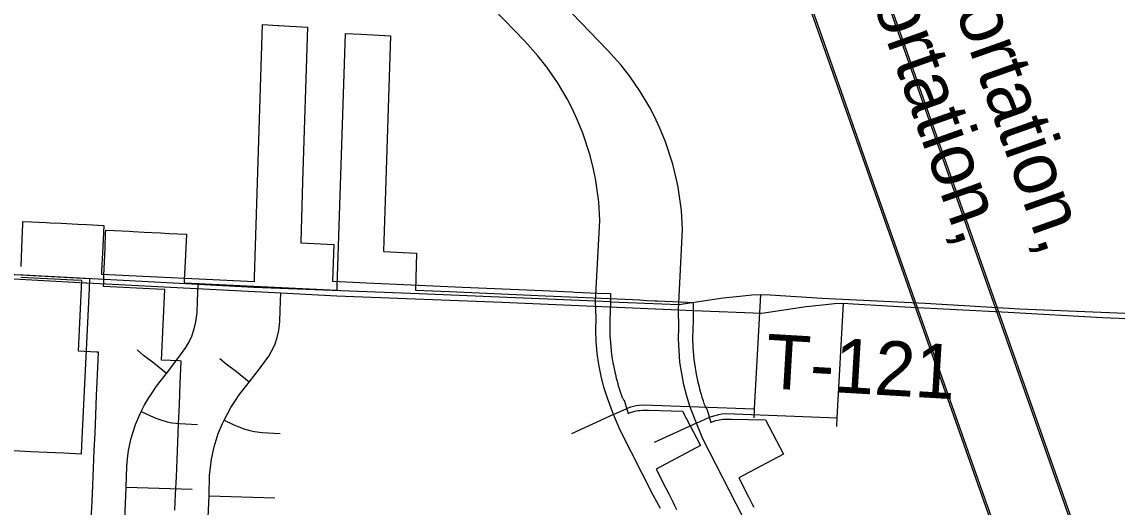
# Model space of a CAD drawing. Extents: x -38.2 to 41.9, y -4 to 24.9.
# Drawn here: x 5.806 to 6.95, y 18.257 to 18.764 of the extents above; entities that cross this region are included whole.
import ezdxf

# ---------------------------------------------------------------- set-up
doc = ezdxf.new("R2010")
doc.units = 0
for name, color, linetype in [('Default', 7, 'Continuous'), ('GM_X_City_Street', 7, 'Continuous'), ('GM_X_County_Road', 7, 'Continuous'), ('GM_X_Interstate_Location', 7, 'Continuous'), ('GM_X_Rail_Line', 7, 'Continuous'), ('GM_X_Rail_Line_Text', 7, 'Continuous'), ('GM_X_State_Location', 7, 'Continuous'), ('GM_X_Township_Road', 7, 'Continuous'), ('GM_X_Township_Road_Text', 7, 'Continuous')]:
    doc.layers.add(name, color=color, linetype=linetype)

msp = doc.modelspace()

# ---------------------------------------------------------------- linework, layer by layer
at = {"layer": 'Default'}
for points in [[(5.8055, 18.5083), (5.8066, 18.537), (5.8072, 18.5526), (5.8073, 18.5556), (5.8162, 18.5551), (5.8317, 18.5544), (5.8358, 18.5541), (5.8473, 18.5536), (5.8646, 18.5527), (5.8739, 18.5522), (5.8918, 18.5513), (5.8904, 18.5224), (5.8894, 18.5041), (5.8895, 18.5013), (5.8895, 18.5005), (6.0491, 18.4929), (6.0492, 18.4962), (6.0493, 18.4969), (6.0576, 18.761), (6.074, 18.7601), (6.0745, 18.7601), (6.1047, 18.7584), (6.0995, 18.5968), (6.0975, 18.534), (6.0975, 18.5333), (6.1319, 18.5315), (6.1307, 18.4931), (6.1663, 18.4914), (6.1974, 18.49), (6.2665, 18.487), (6.3499, 18.4834), (6.3653, 18.4827), (6.3726, 18.4823), (6.381, 18.4819), (6.3834, 18.4818), (6.3919, 18.4814), (6.4076, 18.4807), (6.4211, 18.4801), (6.421, 18.4726), (6.4208, 18.4597), (6.4205, 18.4541), (6.4204, 18.4496), (6.4203, 18.4451), (6.4204, 18.4405), (6.4205, 18.436), (6.4206, 18.433), (6.4209, 18.4292), (6.4213, 18.4247), (6.4217, 18.4202), (6.4222, 18.4164), (6.4229, 18.412), (6.4235, 18.4078), (6.424, 18.4053), (6.4248, 18.4016), (6.4254, 18.3986), (6.4255, 18.3982), (6.4261, 18.3957), (6.427, 18.392), (6.4276, 18.3898), (6.4286, 18.3862), (6.4292, 18.384), (6.4301, 18.3811), (6.4313, 18.3775), (6.4323, 18.3747), (6.4333, 18.3718), (6.4336, 18.3713), (6.4339, 18.3705), (6.4342, 18.37), (6.4347, 18.3694), (6.4352, 18.369), (6.4394, 18.3549), (6.4408, 18.3555), (6.4429, 18.3563), (6.4443, 18.3567), (6.4465, 18.3573), (6.448, 18.3576), (6.4503, 18.358), (6.4518, 18.3582), (6.4543, 18.3584), (6.4571, 18.3584), (6.4609, 18.3583), (6.4963, 18.3574), (6.5152, 18.3216), (6.4686, 18.2969), (6.4788, 18.2771), (6.4823, 18.2703), (6.484, 18.267), (6.4843, 18.2664), (6.4861, 18.2629), (6.488, 18.2588), (6.4899, 18.2547)], [(5.8787, 18.2442), (5.8796, 18.2631), (5.8803, 18.2801), (5.8811, 18.2981), (5.8819, 18.3162), (5.8827, 18.3343), (5.8835, 18.3534), (5.8843, 18.3737), (5.8852, 18.3954), (5.8862, 18.4189), (5.8843, 18.419), (5.8654, 18.4199), (5.869, 18.4938), (5.8603, 18.4941), (5.805, 18.4969)]]:
    msp.add_lwpolyline(points, dxfattribs=at)
at = {"layer": 'GM_X_City_Street'}
msp.add_lwpolyline([(6.7498, 18.4701), (6.8485, 18.4643), (7.0945, 18.4542)], dxfattribs=at)
at = {"layer": 'GM_X_County_Road'}
for points in [[(6.4055, 18.4725), (6.4099, 18.5565), (6.4087, 18.5761), (6.4053, 18.6004), (6.4033, 18.61), (6.3997, 18.6243), (6.3921, 18.6477), (6.3863, 18.662), (6.3803, 18.6748), (6.3757, 18.6835), (6.3656, 18.7004), (6.3544, 18.7166), (6.3453, 18.7283), (6.3316, 18.7436), (6.2668, 18.811)], [(5.966, 18.2539), (5.9668, 18.2709), (5.9676, 18.2889), (5.9684, 18.307), (5.9691, 18.3251), (5.9699, 18.3442), (5.9708, 18.3645), (5.9717, 18.3862), (5.9727, 18.4097), (5.9708, 18.4098), (5.9519, 18.4107), (5.9555, 18.4846), (5.9468, 18.4849), (5.8914, 18.4877), (5.8917, 18.4915), (5.8918, 18.4953), (5.8918, 18.496), (5.892, 18.4991), (5.8931, 18.5278), (5.8937, 18.5434), (5.8938, 18.5464), (5.9027, 18.5459), (5.9182, 18.5452), (5.9223, 18.545), (5.9338, 18.5444), (5.9511, 18.5435), (5.9604, 18.543), (5.9782, 18.5421), (5.9768, 18.5132), (5.9759, 18.4949), (5.9759, 18.4921), (5.976, 18.4914), (6.1356, 18.4837), (6.1357, 18.487), (6.1357, 18.4877), (6.1441, 18.7518), (6.1605, 18.7509), (6.161, 18.7509), (6.1911, 18.7492), (6.186, 18.5876), (6.184, 18.5248), (6.184, 18.5241), (6.2184, 18.5223), (6.2172, 18.4839), (6.2528, 18.4823), (6.2839, 18.4808), (6.353, 18.4778), (6.4364, 18.4742), (6.4518, 18.4735), (6.4591, 18.4731), (6.4675, 18.4727), (6.4699, 18.4726), (6.4783, 18.4722), (6.4941, 18.4715), (6.5075, 18.471), (6.5075, 18.4634), (6.5073, 18.4505), (6.507, 18.4449), (6.5069, 18.4404), (6.5068, 18.4359), (6.5068, 18.4313), (6.507, 18.4268), (6.5071, 18.4238), (6.5074, 18.42), (6.5077, 18.4155), (6.5082, 18.411), (6.5087, 18.4073), (6.5093, 18.4028), (6.51, 18.3986), (6.5105, 18.3961), (6.5112, 18.3924), (6.5119, 18.3894), (6.512, 18.3891), (6.5125, 18.3865), (6.5135, 18.3828), (6.514, 18.3806), (6.5151, 18.377), (6.5157, 18.3748), (6.5166, 18.3719), (6.5177, 18.3683), (6.5187, 18.3655), (6.5198, 18.3626), (6.5201, 18.3621), (6.5204, 18.3613), (6.5207, 18.3608), (6.5212, 18.3602), (6.5216, 18.3598), (6.5258, 18.3457), (6.5272, 18.3463), (6.5294, 18.3471), (6.5308, 18.3475), (6.533, 18.3481), (6.5345, 18.3484), (6.5367, 18.3488), (6.5382, 18.349), (6.5408, 18.3492), (6.5435, 18.3492), (6.5474, 18.3491), (6.5828, 18.3482), (6.6017, 18.3124), (6.5551, 18.2877), (6.5652, 18.2679), (6.5688, 18.2611), (6.5705, 18.2578), (6.5708, 18.2572)], [(5.7734, 18.5014), (5.8243, 18.4987), (5.877, 18.496), (5.8768, 18.4922), (5.8766, 18.4885), (5.8764, 18.4856), (5.8686, 18.3214), (5.8682, 18.3125), (5.8502, 18.3134), (5.8328, 18.3142), (5.8155, 18.3151), (5.7979, 18.316)], [(6.4731, 18.2557), (6.4657, 18.2698), (6.431, 18.3376), (6.4243, 18.3541), (6.4179, 18.3709), (6.4142, 18.3824), (6.4112, 18.3941), (6.4089, 18.406), (6.4072, 18.4179), (6.4061, 18.43), (6.4057, 18.442), (6.4059, 18.4541), (6.4055, 18.4725)]]:
    msp.add_lwpolyline(points, dxfattribs=at)
at = {"layer": 'GM_X_Interstate_Location'}
msp.add_lwpolyline([(6.8363, 18.4609), (6.9349, 18.4551), (7.1809, 18.445)], dxfattribs=at)
at = {"layer": 'GM_X_Rail_Line'}
for points in [[(6.8238, 18.2274), (6.6916, 18.6019), (6.6556, 18.7042), (6.5754, 18.9317), (6.5324, 19.0537), (6.5096, 19.1262), (6.4927, 19.1878), (6.4802, 19.2376), (6.4713, 19.2763), (6.4633, 19.3152), (6.4547, 19.3594), (6.4449, 19.4193), (6.4372, 19.4766)], [(6.8256, 18.228), (6.6934, 18.6025), (6.6574, 18.7048), (6.5772, 18.9323), (6.5342, 19.0543), (6.5115, 19.1267), (6.4945, 19.1883), (6.482, 19.238), (6.4731, 19.2767), (6.4651, 19.3156), (6.4565, 19.3597), (6.4468, 19.4196), (6.439, 19.4768)]]:
    msp.add_lwpolyline(points, dxfattribs=at)
at = {"layer": 'GM_X_Rail_Line_Text'}
for points in [[(6.9103, 18.2182), (6.7781, 18.5927), (6.742, 18.695), (6.6619, 18.9225), (6.6189, 19.0445), (6.5961, 19.117), (6.5791, 19.1786), (6.5667, 19.2284), (6.5578, 19.2671), (6.5497, 19.306), (6.5411, 19.3502), (6.5313, 19.4101), (6.5236, 19.4674)], [(6.912, 18.2188), (6.7799, 18.5933), (6.7438, 18.6956), (6.6637, 18.9231), (6.6207, 19.0451), (6.5979, 19.1175), (6.581, 19.1791), (6.5685, 19.2289), (6.5596, 19.2675), (6.5516, 19.3064), (6.543, 19.3505), (6.5332, 19.4104), (6.5255, 19.4676)]]:
    msp.add_lwpolyline(points, dxfattribs=at)
at = {"layer": 'GM_X_State_Location'}
for p, q in [((5.8741, 18.4914), (5.8939, 18.4904)), ((6.492, 18.4633), (6.5069, 18.4626)), ((6.5108, 18.345), (6.4668, 18.3247)), ((6.0017, 18.2689), (6.0705, 18.2669))]:
    msp.add_line(p, q, dxfattribs=at)
for points in [[(5.6407, 18.5041), (5.8731, 18.4915), (5.8741, 18.4914)], [(5.8939, 18.4904), (6.0768, 18.4809), (6.1351, 18.4778), (6.3078, 18.4712), (6.492, 18.4633)], [(5.9988, 18.2016), (6.0017, 18.2689), (6.0022, 18.2906), (6.0032, 18.2986), (6.0042, 18.3073), (6.0069, 18.32), (6.0114, 18.3342), (6.0158, 18.3446), (6.0174, 18.3479), (6.0205, 18.354), (6.0246, 18.3611), (6.0287, 18.3675), (6.0333, 18.3743), (6.0438, 18.3877), (6.0555, 18.4031), (6.064, 18.4147), (6.0671, 18.4199), (6.0703, 18.4265), (6.0728, 18.4342), (6.0745, 18.4417), (6.0757, 18.4511), (6.076, 18.463), (6.0768, 18.4809)], [(6.5069, 18.4626), (6.5079, 18.4625), (6.579, 18.4596), (6.6114, 18.4645), (6.6253, 18.4666), (6.6425, 18.4684), (6.6551, 18.4697), (6.6643, 18.4701), (6.6744, 18.4695)], [(6.6574, 18.3414), (6.6579, 18.3506), (6.6643, 18.4701)], [(6.6744, 18.4695), (6.7286, 18.4663), (6.8363, 18.4609)], [(6.0438, 18.3877), (6.0304, 18.3984), (6.0195, 18.4065), (6.013, 18.4121)], [(6.5108, 18.345), (6.5244, 18.3512), (6.5289, 18.3527), (6.5342, 18.354), (6.5375, 18.3545), (6.5416, 18.3548), (6.6579, 18.3506)], [(6.0174, 18.3479), (6.027, 18.3435), (6.0328, 18.341), (6.039, 18.3387), (6.0444, 18.3373), (6.0493, 18.3363), (6.0573, 18.3353), (6.0761, 18.3342)]]:
    msp.add_lwpolyline(points, dxfattribs=at)
at = {"layer": 'GM_X_Township_Road'}
for p, q in [((5.7876, 18.5006), (5.8075, 18.4996)), ((6.4055, 18.4725), (6.4205, 18.4718)), ((6.4243, 18.3541), (6.3804, 18.3339)), ((5.9152, 18.2781), (5.984, 18.2761))]:
    msp.add_line(p, q, dxfattribs=at)
for points in [[(5.8075, 18.4996), (5.9904, 18.4901), (6.0486, 18.487), (6.2213, 18.4804), (6.4055, 18.4725)], [(5.9123, 18.2108), (5.9152, 18.2781), (5.9158, 18.2998), (5.9167, 18.3078), (5.9177, 18.3165), (5.9205, 18.3292), (5.9249, 18.3434), (5.9293, 18.3538), (5.9309, 18.3571), (5.934, 18.3632), (5.9381, 18.3703), (5.9422, 18.3767), (5.9469, 18.3835), (5.9573, 18.3968), (5.969, 18.4123), (5.9775, 18.4239), (5.9806, 18.4291), (5.9839, 18.4357), (5.9863, 18.4434), (5.988, 18.4508), (5.9892, 18.4603), (5.9895, 18.4722), (5.9904, 18.4901)], [(6.4205, 18.4718), (6.4215, 18.4717), (6.4925, 18.4688), (6.5249, 18.4737), (6.5388, 18.4758), (6.556, 18.4776), (6.5686, 18.4789), (6.5779, 18.4793), (6.5879, 18.4787)], [(6.571, 18.3506), (6.5714, 18.3598), (6.5779, 18.4793)], [(6.5879, 18.4787), (6.6421, 18.4755), (6.7498, 18.4701)], [(5.9573, 18.3968), (5.9439, 18.4076), (5.9331, 18.4157), (5.9265, 18.4213)], [(6.4243, 18.3541), (6.438, 18.3603), (6.4424, 18.3619), (6.4477, 18.3632), (6.451, 18.3637), (6.4551, 18.3639), (6.5714, 18.3598)], [(5.9309, 18.3571), (5.9405, 18.3527), (5.9463, 18.3502), (5.9525, 18.3479), (5.9579, 18.3464), (5.9628, 18.3454), (5.9708, 18.3444), (5.9897, 18.3434)]]:
    msp.add_lwpolyline(points, dxfattribs=at)
at = {"layer": 'GM_X_Township_Road_Text'}
for points in [[(6.492, 18.4633), (6.4964, 18.5473), (6.4952, 18.5669), (6.4917, 18.5912), (6.4898, 18.6008), (6.4862, 18.6152), (6.4786, 18.6385), (6.4727, 18.6528), (6.4667, 18.6656), (6.4622, 18.6743), (6.4521, 18.6912), (6.4409, 18.7074), (6.4318, 18.7191), (6.418, 18.7344), (6.3533, 18.8018)], [(6.5596, 18.2465), (6.5522, 18.2606), (6.5175, 18.3284), (6.5108, 18.345), (6.5043, 18.3617), (6.5007, 18.3732), (6.4977, 18.3849), (6.4954, 18.3968), (6.4936, 18.4087), (6.4926, 18.4208), (6.4921, 18.4328), (6.4924, 18.4449), (6.492, 18.4633)]]:
    msp.add_lwpolyline(points, dxfattribs=at)

# ---------------------------------------------------------------- texts
at = {"layer": 'GM_X_City_Street'}
msp.add_text('Transportation,', height=0.056629, rotation=289.4448, dxfattribs=at).set_placement((6.7026, 18.9984))
at = {"layer": 'GM_X_Rail_Line_Text'}
msp.add_text('Transportation,', height=0.056629, rotation=289.4448, dxfattribs=at).set_placement((6.6162, 19.0076))
at = {"layer": 'GM_X_Township_Road_Text'}
msp.add_text('T-121', height=0.05682, rotation=356.6293, dxfattribs=at).set_placement((6.5818, 18.3815))

doc.saveas('drawing.dxf')
